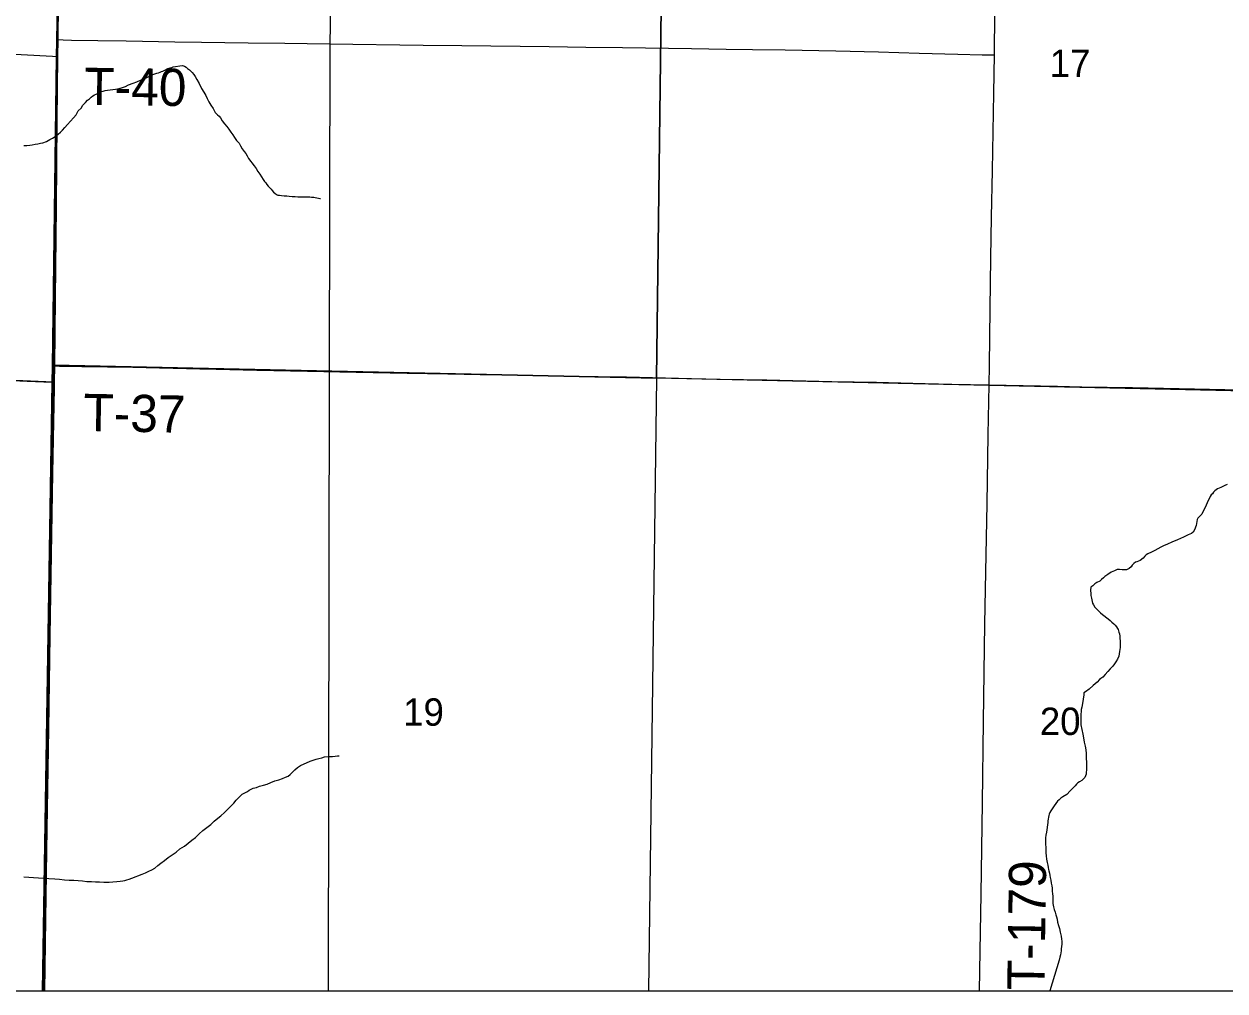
# Model space of a CAD drawing. Extents: x 0 to 68, y 0 to 52.9.
# Drawn here: x 43.796 to 45.735, y 31.143 to 32.704 of the extents above; entities that cross this region are included whole.
import ezdxf

# ---------------------------------------------------------------- set-up
doc = ezdxf.new("R2010")
doc.units = 0
for name, color, linetype in [('Default', 7, 'Continuous'), ('GM_X_County_Road', 7, 'Continuous'), ('GM_X_Minor_River', 7, 'Continuous'), ('GM_X_Township', 7, 'Continuous'), ('GM_X_Township_Road', 7, 'Continuous'), ('GM_X_Township_Road_Text', 7, 'Continuous')]:
    doc.layers.add(name, color=color, linetype=linetype)

msp = doc.modelspace()

# ---------------------------------------------------------------- linework, layer by layer
at = {"layer": 'Default'}
msp.add_line((42.2581, 31.1431), (49.6501, 31.1431), dxfattribs=at)
for points in [[(44.2873, 31.1431), (44.2887, 32.1425), (44.2897, 32.6711), (44.2988, 33.2072), (44.3083, 33.7351), (44.3156, 34.0851), (44.3228, 34.4048)], [(43.829, 31.1431), (43.8314, 31.2964), (43.8332, 31.4047), (43.8359, 31.5654), (43.8381, 31.7164), (43.8422, 31.9789), (43.8448, 32.1166), (43.8449, 32.1251), (43.8452, 32.1517), (43.8465, 32.261), (43.848, 32.4087), (43.8494, 32.5465), (43.8505, 32.651), (43.8508, 32.6785), (43.851, 32.6942), (43.8525, 32.7729)], [(43.8269, 31.1431), (43.8431, 32.1253), (43.8439, 32.1529), (44.8166, 32.1321), (44.804, 31.1431)]]:
    msp.add_lwpolyline(points, dxfattribs=at)
for points in [[(42.7855, 33.2374), (43.8558, 33.1813), (43.8439, 32.1529), (43.8431, 32.1253), (42.7704, 32.1726)], [(43.8561, 33.2057), (44.3286, 33.2092), (44.8302, 33.199), (44.8166, 32.1321), (43.8439, 32.1529), (43.8558, 33.1813)], [(44.8302, 33.199), (45.9077, 33.1703), (45.8901, 32.1083), (44.8166, 32.1321)]]:
    msp.add_lwpolyline(points, close=True, dxfattribs=at)
at = {"layer": 'GM_X_County_Road'}
for points in [[(43.3098, 32.6781), (43.387, 32.6746), (43.478, 32.6695), (43.5861, 32.6642), (43.7499, 32.6564), (43.8417, 32.6515), (43.8505, 32.651)], [(43.3115, 32.1493), (43.3254, 32.1485), (43.3549, 32.1476), (43.5057, 32.1406), (43.568, 32.1377), (43.6566, 32.1339), (43.8008, 32.1272), (43.841, 32.1253), (43.8449, 32.1251)]]:
    msp.add_lwpolyline(points, dxfattribs=at)
at = {"layer": 'GM_X_Minor_River'}
for points in [[(43.7952, 32.5074), (43.798, 32.5073), (43.8004, 32.5077), (43.8048, 32.5081), (43.8088, 32.5088), (43.8137, 32.5096), (43.8181, 32.5103), (43.8221, 32.5111), (43.8258, 32.5119), (43.8322, 32.5142), (43.8346, 32.5158), (43.8375, 32.5174), (43.8415, 32.5193), (43.8443, 32.5209), (43.8472, 32.5233), (43.8508, 32.5257), (43.8545, 32.5288), (43.8577, 32.5324), (43.8614, 32.5364), (43.8658, 32.5416), (43.8707, 32.5468), (43.8756, 32.5519), (43.8797, 32.5571), (43.8833, 32.5635), (43.8878, 32.5679), (43.8907, 32.5727), (43.8947, 32.5771), (43.8984, 32.5806), (43.9012, 32.583), (43.9041, 32.5854), (43.9069, 32.5878), (43.9093, 32.589), (43.9121, 32.5901), (43.917, 32.5929), (43.9202, 32.5945), (43.9234, 32.5952), (43.9267, 32.596), (43.9303, 32.5968), (43.9347, 32.5971), (43.9391, 32.5979), (43.9436, 32.5982), (43.9492, 32.5994), (43.9545, 32.6009), (43.9593, 32.6025), (43.9641, 32.6053), (43.9718, 32.608), (43.9779, 32.6103), (43.9835, 32.6127), (43.9892, 32.6147), (43.994, 32.6174), (44.0001, 32.6202), (44.0053, 32.6225), (44.0101, 32.6241), (44.013, 32.6249), (44.0154, 32.6256), (44.0174, 32.6268), (44.0198, 32.6276), (44.0239, 32.6296), (44.0259, 32.6307), (44.0279, 32.6315), (44.0315, 32.6327), (44.0344, 32.6335), (44.0364, 32.6343), (44.0404, 32.635), (44.0472, 32.6362), (44.0517, 32.6365), (44.0545, 32.6353), (44.0573, 32.634), (44.0597, 32.6316), (44.0629, 32.6296), (44.0652, 32.6275), (44.0672, 32.6255), (44.07, 32.6223), (44.072, 32.619), (44.0748, 32.6142), (44.0783, 32.6073), (44.0823, 32.5996), (44.0862, 32.5936), (44.089, 32.5883), (44.0913, 32.5834), (44.0941, 32.5782), (44.0973, 32.5725), (44.1008, 32.5673), (44.104, 32.5608), (44.108, 32.5572), (44.1108, 32.5547), (44.1127, 32.5519), (44.1155, 32.5474), (44.1191, 32.5426), (44.1231, 32.5381), (44.1262, 32.5337), (44.1298, 32.5292), (44.133, 32.5247), (44.1357, 32.5203), (44.1389, 32.5158), (44.1429, 32.511), (44.1453, 32.5069), (44.148, 32.5021)], [(44.148, 32.5021), (44.1508, 32.498), (44.1536, 32.4944), (44.1559, 32.4908), (44.1583, 32.4867), (44.1674, 32.4746), (44.1702, 32.4705), (44.173, 32.4653), (44.1766, 32.4612), (44.1789, 32.4568), (44.1817, 32.4527), (44.1841, 32.4495), (44.1861, 32.447), (44.1876, 32.4446), (44.19, 32.4418), (44.192, 32.4397), (44.1948, 32.4369), (44.1964, 32.4349), (44.1984, 32.4324), (44.2004, 32.4304), (44.2032, 32.4284), (44.2056, 32.4275), (44.208, 32.4271), (44.2116, 32.4267), (44.2156, 32.4262), (44.22, 32.4262), (44.2236, 32.4257), (44.2285, 32.4253), (44.2333, 32.4252), (44.2377, 32.4248), (44.2425, 32.4247), (44.2465, 32.4247), (44.2502, 32.4247), (44.2538, 32.4246), (44.257, 32.4246), (44.2598, 32.4242), (44.2634, 32.4241), (44.2658, 32.4237), (44.2686, 32.4229), (44.271, 32.4224), (44.273, 32.422), (44.2742, 32.422)], [(45.7381, 31.9604), (45.7341, 31.9588), (45.7309, 31.9572), (45.7277, 31.9556), (45.7249, 31.9544), (45.7225, 31.9532), (45.7205, 31.952), (45.718, 31.95), (45.716, 31.948), (45.7144, 31.9452), (45.7124, 31.9436), (45.7108, 31.9412), (45.7096, 31.9384), (45.7076, 31.9344), (45.7043, 31.9272), (45.6971, 31.9123), (45.6906, 31.9063), (45.6894, 31.9039), (45.6878, 31.8943), (45.6854, 31.8871), (45.683, 31.8835), (45.6805, 31.8815), (45.6753, 31.8791), (45.6677, 31.8755), (45.658, 31.8711), (45.6488, 31.8671)], [(45.6488, 31.8671), (45.6416, 31.864), (45.6355, 31.8616), (45.6307, 31.8592), (45.6259, 31.8568), (45.6211, 31.854), (45.6159, 31.8512), (45.6102, 31.8484), (45.6074, 31.8468), (45.605, 31.8448), (45.6022, 31.8416), (45.5974, 31.838), (45.5921, 31.8356), (45.5901, 31.8352), (45.5873, 31.8332), (45.5849, 31.83), (45.5833, 31.8276), (45.5797, 31.8248), (45.5753, 31.8228), (45.5724, 31.8228), (45.5704, 31.8229), (45.5684, 31.8229), (45.564, 31.8233), (45.5604, 31.8233), (45.556, 31.8213), (45.5508, 31.8189), (45.5455, 31.8153), (45.5407, 31.8121), (45.5383, 31.8097), (45.5351, 31.8069), (45.5323, 31.8045), (45.5278, 31.8021), (45.5242, 31.8001), (45.521, 31.7969), (45.5182, 31.7945), (45.5174, 31.7901), (45.5174, 31.7881), (45.5178, 31.7857), (45.5182, 31.7813), (45.519, 31.7769), (45.5197, 31.7741), (45.5201, 31.7717), (45.5209, 31.7688), (45.5225, 31.7664), (45.5245, 31.7624), (45.5277, 31.7592), (45.5305, 31.7564), (45.5337, 31.7531), (45.5369, 31.7507), (45.5462, 31.7435), (45.549, 31.7411), (45.5518, 31.7382), (45.555, 31.7354), (45.5574, 31.7334), (45.5594, 31.7306), (45.561, 31.7282), (45.5622, 31.7262), (45.5634, 31.7222), (45.5642, 31.7193), (45.5646, 31.7157), (45.565, 31.7121), (45.5653, 31.7081), (45.5653, 31.7033), (45.5653, 31.6973), (45.5641, 31.6908), (45.5629, 31.6836), (45.5609, 31.6784), (45.5584, 31.6744), (45.556, 31.6708), (45.5532, 31.6672), (45.5492, 31.6632), (45.5456, 31.6584), (45.5411, 31.6536), (45.5371, 31.6496), (45.5339, 31.6476), (45.5319, 31.6456), (45.5283, 31.6416), (45.5218, 31.636), (45.515, 31.63), (45.5094, 31.6256), (45.5069, 31.624), (45.5065, 31.6212), (45.5057, 31.614), (45.5045, 31.6068), (45.5033, 31.6012), (45.5025, 31.5971), (45.5021, 31.5935), (45.5016, 31.5903), (45.5016, 31.5867), (45.5016, 31.5819), (45.5016, 31.5771), (45.502, 31.5727), (45.5048, 31.5574), (45.506, 31.5514), (45.5072, 31.5446), (45.5087, 31.5381), (45.5099, 31.5321), (45.5103, 31.5261), (45.5103, 31.5193), (45.5107, 31.5112), (45.5107, 31.5024)], [(44.035, 31.3628), (44.0415, 31.3671), (44.0472, 31.3723), (44.0549, 31.377), (44.0605, 31.3814), (44.0666, 31.3862), (44.0723, 31.3909), (44.0784, 31.3965), (44.0845, 31.402), (44.0909, 31.4068), (44.097, 31.412), (44.1027, 31.4171), (44.1084, 31.4219), (44.1132, 31.4259), (44.1193, 31.431), (44.1242, 31.4362), (44.1295, 31.4414), (44.1343, 31.4461), (44.1384, 31.4509), (44.1429, 31.4561), (44.1481, 31.4605), (44.153, 31.4632), (44.1562, 31.4652), (44.1591, 31.4672), (44.1623, 31.4687), (44.1655, 31.4703), (44.1708, 31.4715), (44.176, 31.4734), (44.1825, 31.475), (44.1881, 31.4769), (44.1942, 31.4797), (44.2006, 31.482), (44.2071, 31.484), (44.2131, 31.4859), (44.218, 31.4879), (44.222, 31.4898), (44.2252, 31.4926), (44.2293, 31.4962), (44.2329, 31.4998), (44.237, 31.5037), (44.2419, 31.5069), (44.2576, 31.514), (44.2624, 31.5155), (44.2673, 31.5171), (44.2717, 31.5182), (44.2762, 31.5194), (44.281, 31.521), (44.2882, 31.5213), (44.2935, 31.5216), (44.2979, 31.522), (44.3015, 31.5224), (44.3043, 31.5223), (44.3047, 31.5223)], [(45.5107, 31.5024), (45.5106, 31.4932), (45.5082, 31.4876), (45.5034, 31.4828), (45.4998, 31.4804), (45.497, 31.4788), (45.4949, 31.4768), (45.4925, 31.4744), (45.4893, 31.4708), (45.4845, 31.466), (45.4793, 31.46), (45.4728, 31.4564), (45.4696, 31.454), (45.4668, 31.4516), (45.4644, 31.4492), (45.4616, 31.4456), (45.4587, 31.4416), (45.4555, 31.4372), (45.4535, 31.434), (45.4519, 31.4312), (45.4507, 31.4284), (45.4499, 31.4264), (45.4495, 31.4236), (45.4491, 31.4203), (45.4486, 31.4175), (45.4486, 31.4147), (45.4462, 31.3995), (45.4454, 31.3943), (45.445, 31.3903), (45.445, 31.387), (45.445, 31.383), (45.4449, 31.3794), (45.4453, 31.375), (45.4453, 31.3706), (45.4453, 31.3662), (45.4457, 31.3614), (45.4465, 31.3557), (45.4473, 31.3505), (45.4485, 31.3461), (45.4489, 31.3425), (45.4497, 31.3393), (45.4501, 31.3369), (45.4513, 31.3333), (45.4516, 31.3296), (45.4524, 31.326), (45.4532, 31.322), (45.454, 31.3172), (45.4548, 31.3128), (45.4556, 31.3088), (45.4556, 31.3039), (45.456, 31.2999), (45.4564, 31.2959), (45.4564, 31.2923), (45.4564, 31.2883), (45.4567, 31.2843), (45.4575, 31.2791), (45.4587, 31.2746), (45.4603, 31.2702), (45.4615, 31.2662), (45.4627, 31.2626), (45.4635, 31.259), (45.4643, 31.2542), (45.4659, 31.2489), (45.4671, 31.2437), (45.4683, 31.2381), (45.4699, 31.2313), (45.4707, 31.2268), (45.471, 31.2232), (45.471, 31.2188), (45.4706, 31.2148), (45.4702, 31.2112), (45.4698, 31.208), (45.4694, 31.2044), (45.469, 31.2012), (45.4678, 31.1976), (45.4666, 31.1928), (45.452, 31.1431)], [(43.7955, 31.3271), (43.8032, 31.3266), (43.8108, 31.3261), (43.8188, 31.3256), (43.8273, 31.3252), (43.8357, 31.3247), (43.8453, 31.3238), (43.853, 31.3233), (43.861, 31.3224), (43.8686, 31.3219), (43.8759, 31.3218), (43.8831, 31.3214), (43.8903, 31.3209), (43.8971, 31.32), (43.9044, 31.3195), (43.9112, 31.3191), (43.9176, 31.319), (43.9245, 31.3189), (43.9333, 31.3188), (43.9393, 31.3192), (43.9454, 31.3195), (43.951, 31.3202), (43.9554, 31.3206), (43.9583, 31.3214), (43.9615, 31.3226), (43.9655, 31.3237), (43.9699, 31.3249), (43.9865, 31.3315), (43.9917, 31.3339), (43.997, 31.3362), (44.0018, 31.3386), (44.0067, 31.3414), (44.0115, 31.3453), (44.0168, 31.3493), (44.0225, 31.3537), (44.0286, 31.3584), (44.035, 31.3628)]]:
    msp.add_lwpolyline(points, dxfattribs=at)
at = {"layer": 'GM_X_Township'}
msp.add_lwpolyline([(43.8255, 31.1431), (43.8412, 32.1252), (43.8416, 32.1514), (43.848, 32.6506), (43.8484, 32.6776), (43.8577, 33.1798), (43.8583, 33.2049), (43.8631, 33.7395), (43.8693, 34.2426), (43.8728, 34.5425), (43.8742, 34.7352), (43.8773, 34.8686), (43.8737, 34.9229), (43.874, 34.9402), (43.8796, 35.1936), (43.8797, 35.2152), (43.8798, 35.2893), (44.0257, 35.2866), (44.0303, 35.2868), (44.6712, 35.2829), (45.1961, 35.2737), (45.9849, 35.2547)], dxfattribs=at)
at = {"layer": 'GM_X_Township_Road'}
for points in [[(45.3624, 32.6536), (45.3626, 32.6641), (45.3643, 32.8085), (45.3672, 32.9529), (45.3693, 33.094), (45.3709, 33.1858)], [(43.8508, 32.6785), (43.8589, 32.6781), (43.8721, 32.6776), (43.9147, 32.677), (43.9607, 32.6763), (44.0394, 32.6748), (44.0821, 32.6743), (44.1576, 32.673), (44.2167, 32.6725), (44.2889, 32.6715), (44.4399, 32.6695), (44.5023, 32.669), (44.6435, 32.667), (44.7026, 32.6661), (44.7617, 32.6654), (44.8733, 32.6639), (44.9291, 32.6628), (44.9718, 32.6625), (45.0243, 32.6621), (45.1064, 32.6602), (45.1753, 32.6587), (45.2409, 32.6566), (45.3033, 32.6551), (45.3427, 32.6536), (45.3558, 32.6536), (45.3624, 32.6536)], [(45.3537, 32.1212), (45.3542, 32.1522), (45.3556, 32.2441), (45.3567, 32.3262), (45.3575, 32.3918), (45.3593, 32.4672), (45.3611, 32.5919), (45.3624, 32.6536)], [(43.8452, 32.1517), (43.8532, 32.1515), (43.8892, 32.1507), (43.9713, 32.1496), (44.0795, 32.147), (44.1058, 32.1466), (44.1714, 32.145), (44.2534, 32.1432), (44.3321, 32.1417), (44.4141, 32.14), (44.4798, 32.1392), (44.5322, 32.1382), (44.5782, 32.1375), (44.6766, 32.1355), (44.7685, 32.134), (44.8735, 32.1317), (44.9194, 32.1304), (44.9949, 32.1291), (45.0998, 32.1268), (45.172, 32.1255), (45.2507, 32.1236), (45.2933, 32.1224), (45.3537, 32.1212)], [(45.3382, 31.1431), (45.3394, 31.2072), (45.3408, 31.2991), (45.3431, 31.4467), (45.3448, 31.578), (45.347, 31.7355), (45.3492, 31.8471), (45.3504, 31.9291), (45.3523, 32.0407), (45.3537, 32.1212)], [(45.3537, 32.1212), (45.4639, 32.1189), (45.5033, 32.1183), (45.5853, 32.1167), (45.6607, 32.1155), (45.7592, 32.1133), (45.8313, 32.1119), (45.9494, 32.1088), (46.0019, 32.108), (46.1266, 32.1042), (46.2348, 32.101), (46.2676, 32.1), (46.284, 32.0999), (46.3496, 32.0978), (46.4644, 32.0947), (46.5891, 32.0917), (46.6743, 32.0902), (46.7137, 32.0894), (46.8023, 32.0865), (46.904, 32.0833), (46.9498, 32.0816), (46.958, 32.0816)]]:
    msp.add_lwpolyline(points, dxfattribs=at)

# ---------------------------------------------------------------- texts
at = {"layer": 'Default'}
for s, p in [('17', (45.4515, 32.618)), ('19', (44.4078, 31.5711)), ('20', (45.4356, 31.5562))]:
    msp.add_text(s, height=0.0442, rotation=0, dxfattribs=at).set_placement(p)
at = {"layer": 'GM_X_Township_Road_Text'}
for s, rotation, p in [('T-40', 359.2931, (43.8926, 32.5731)), ('T-37', 358.9397, (43.891, 32.0469)), ('T-179', 89.1634, (45.4429, 31.1439))]:
    msp.add_text(s, height=0.06, rotation=rotation, dxfattribs=at).set_placement(p)

doc.saveas('drawing.dxf')
